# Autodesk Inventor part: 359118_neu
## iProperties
Created: 2006-10
Part Number: 359118_neu
Material: 1.0330.03
Description: Scheibe
Document SubType Name: Modeling
Designer: OSchmidt
Density: 7.84 g/cm^3
Mass: 39.3948 g
Surface Area: 40.414 cm^2
Volume: 5.02485 cm^3
Abmessung: Bl.1,5
HalbzeugNorm: DIN 1541
Author: Natti_01
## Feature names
1. Extrusion1
